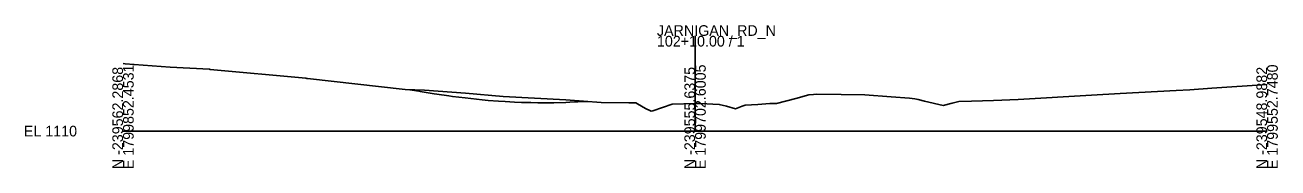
# Model space of a CAD drawing. Extents: x 214513 to 217151, y 214739 to 216780.
# Drawn here: x 216822.7 to 217151.2, y 215238.7 to 215276.2 of the extents above; entities that cross this region are included whole.
import ezdxf

# ---------------------------------------------------------------- set-up
doc = ezdxf.new("R2010")
doc.units = 0
for name, color, linetype in [('DESIGN - DRAINAGE - Special Ditches', 7, 'Continuous'), ('DESIGN - EARTHWORK - Shapes', 7, 'Continuous'), ('Section', 7, 'Continuous'), ('SURVEY - DTM GRAPHICS - Triangles', 7, 'Continuous'), ('XSCell', 7, 'Continuous')]:
    doc.layers.add(name, color=color, linetype=linetype)

msp = doc.modelspace()

# ---------------------------------------------------------------- linework, layer by layer
at = {"layer": 'DESIGN - DRAINAGE - Special Ditches'}
msp.add_lwpolyline([(216970.23, 215256.17), (216969.84, 215256.14), (216969.71, 215256.13), (216965.54, 215255.92), (216964.44, 215255.89), (216961.3, 215255.81), (216959.69, 215255.81), (216957.09, 215255.8), (216955.26, 215255.85), (216952.86, 215255.9), (216951.01, 215255.99), (216948.55, 215256.11), (216946.81, 215256.24), (216944.14, 215256.43), (216942.5, 215256.59), (216939.55, 215256.88), (216938.12, 215257.05), (216934.72, 215257.47), (216933.8, 215257.6), (216930.63, 215258.05), (216929.96, 215258.15), (216926.3, 215258.74), (216925.96, 215258.8), (216923.55, 215259.23)], dxfattribs=at)
at = {"layer": 'DESIGN - EARTHWORK - Shapes'}
msp.add_line((216923.66, 215259.21), (216925.96, 215258.8), dxfattribs=at)
for points in [[(216970.23, 215256.17), (216964.47, 215256.6), (216948.06, 215257.47), (216938.18, 215258.31), (216927.44, 215259.09), (216923.66, 215259.21)], [(216925.96, 215258.8), (216926.3, 215258.74), (216929.96, 215258.15), (216930.63, 215258.05), (216933.8, 215257.6), (216934.72, 215257.47), (216938.12, 215257.05), (216939.55, 215256.88), (216942.5, 215256.59), (216944.14, 215256.43), (216946.81, 215256.24), (216948.55, 215256.11), (216951.01, 215255.99), (216952.86, 215255.9), (216955.26, 215255.85), (216957.09, 215255.8), (216959.69, 215255.81), (216961.3, 215255.81), (216964.44, 215255.89), (216965.54, 215255.92), (216969.71, 215256.13), (216969.84, 215256.14), (216970.23, 215256.17)]]:
    msp.add_lwpolyline(points, dxfattribs=at)
at = {"layer": 'SURVEY - DTM GRAPHICS - Triangles'}
msp.add_lwpolyline([(216848.36, 215266.08), (216848.91, 215266.01), (216860.74, 215265.1), (216871.04, 215264.58), (216871.25, 215264.57), (216896.32, 215262.21), (216896.52, 215262.19), (216896.63, 215262.18), (216896.73, 215262.16), (216922.34, 215259.25), (216927.44, 215259.09), (216938.18, 215258.31), (216948.06, 215257.47), (216964.47, 215256.6), (216973.77, 215255.9), (216980.96, 215255.8), (216982.87, 215255.75), (216984.79, 215254.66), (216985.58, 215254.24), (216986.49, 215253.74), (216986.85, 215253.57), (216987.33, 215253.71), (216992.32, 215255.4), (216998.43, 215255.56), (216999.11, 215255.57), (216999.78, 215255.56), (217004.71, 215255.37), (217006.64, 215254.87), (217008.99, 215254.21), (217010.72, 215254.87), (217011.54, 215255.18), (217014.81, 215255.33), (217017.94, 215255.56), (217019.05, 215255.57), (217019.74, 215255.58), (217024.75, 215256.91), (217028.18, 215257.87), (217029.39, 215257.95), (217030.14, 215258.03), (217036.67, 215257.96), (217042.92, 215257.89), (217049.75, 215257.38), (217054.62, 215257.01), (217056.01, 215256.79), (217056.85, 215256.64), (217058.54, 215256.23), (217063.38, 215255.08), (217065.79, 215255.69), (217067.53, 215256.17), (217070.84, 215256.23), (217076.63, 215256.35), (217083.08, 215256.69), (217102.35, 215257.79), (217109.87, 215258.2), (217124.53, 215259.05), (217128.06, 215259.16), (217133.83, 215259.63), (217148.36, 215260.6)], dxfattribs=at)
at = {"layer": 'XSCell'}
for p, q in [((216998.36, 215248.36), (216998.36, 215273.36)), ((216848.36, 215248.36), (216998.36, 215248.36)), ((216998.36, 215248.36), (217148.36, 215248.36))]:
    msp.add_line(p, q, dxfattribs=at)

# ---------------------------------------------------------------- texts
at = {"layer": 'Section'}
msp.add_text('-', height=0.0001, dxfattribs=at).set_placement((216848.36, 215248.36))
at = {"layer": 'XSCell'}
for s, p in [('JARNIGAN_RD_N', (216988.36, 215273.36)), ('102+10.00 / 1', (216988.36, 215270.56)), ('EL 1110', (216822.36, 215246.96))]:
    msp.add_text(s, height=2.8, dxfattribs=at).set_placement(p)
for s, p in [('N -239562.2868', (216848.36, 215238.36)), ('E 1799852.4531', (216851.16, 215238.36)), ('N -239555.6375', (216998.36, 215238.36)), ('E 1799702.6005', (217001.16, 215238.36)), ('N -239548.9882', (217148.36, 215238.36)), ('E 1799552.7480', (217151.16, 215238.36))]:
    msp.add_text(s, height=2.8, rotation=90, dxfattribs=at).set_placement(p)

doc.saveas('drawing.dxf')
